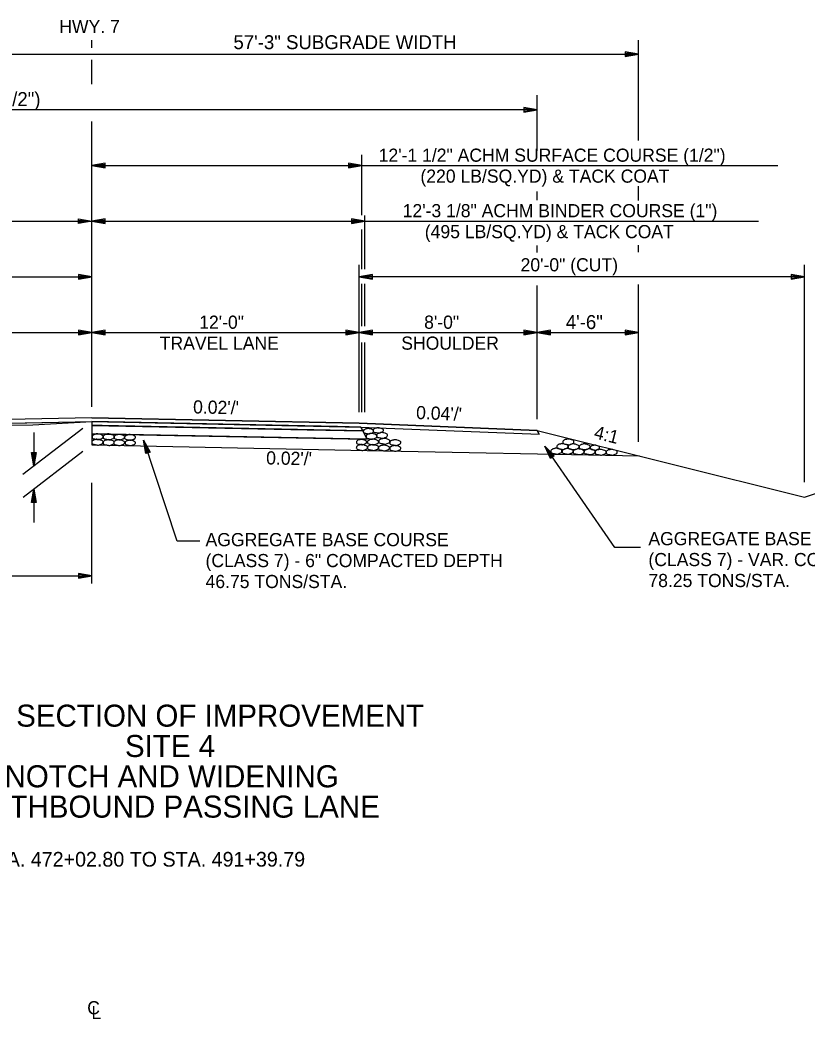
# Model space of a CAD drawing. Extents: x 1398183 to 1398373, y 1967240 to 1968889.
# Drawn here: x 1398250.61 to 1398285.95, y 1967604.2 to 1967649.04 of the extents above; entities that cross this region are included whole.
import ezdxf

# ---------------------------------------------------------------- set-up
doc = ezdxf.new("R2010")
doc.units = 0
for name, color, linetype in [('1', 7, 'Continuous'), ('10', 7, 'Continuous'), ('19', 7, 'Continuous'), ('42', 7, 'Continuous'), ('7', 7, 'Continuous'), ('Level 1', 7, 'Continuous')]:
    doc.layers.add(name, color=color, linetype=linetype)

# ---------------------------------------------------------------- blocks, each defined once
blk = doc.blocks.new('ROCKS')
at = {"layer": '1'}
blk.add_spline([(0.013, 0.06), (0.053, 0.053), (0.107, 0.033), (0.133, 0.013), (0.133, -0.007), (0.12, -0.033), (0.107, -0.04), (0.073, -0.053), (0.033, -0.067), (0.013, -0.067), (-0.02, -0.06), (-0.06, -0.053), (-0.087, -0.047), (-0.113, -0.02), (-0.113, -0.007), (-0.107, 0.02), (-0.087, 0.033), (-0.067, 0.047), (-0.033, 0.053), (-0.02, 0.06), (0.013, 0.06)], degree=3, dxfattribs=at)

msp = doc.modelspace()

# ---------------------------------------------------------------- linework, layer by layer
at = {"layer": '19'}
for p, q in [((1398278.376, 1967643.623), (1398278.376, 1967648.126)), ((1398221.092, 1967647.504), (1398278.376, 1967647.504)), ((1398277.776, 1967647.61), (1398277.776, 1967647.4)), ((1398278.376, 1967647.504), (1398277.776, 1967647.61)), ((1398278.216, 1967647.519), (1398277.776, 1967647.555)), ((1398277.776, 1967647.4), (1398278.376, 1967647.504)), ((1398277.776, 1967647.45), (1398278.216, 1967647.489)), ((1398273.831, 1967643.17), (1398273.831, 1967645.662)), ((1398273.231, 1967645.11), (1398273.231, 1967644.9)), ((1398273.831, 1967645.004), (1398273.231, 1967645.11)), ((1398273.671, 1967645.019), (1398273.231, 1967645.055)), ((1398273.831, 1967645.004), (1398223.831, 1967645.005)), ((1398273.231, 1967644.9), (1398273.831, 1967645.004)), ((1398273.231, 1967644.95), (1398273.671, 1967644.989)), ((1398265.966, 1967640.272), (1398265.966, 1967642.987)), ((1398254.438, 1967642.609), (1398253.838, 1967642.504)), ((1398253.838, 1967642.504), (1398254.438, 1967642.399)), ((1398253.838, 1967642.504), (1398284.641, 1967642.504)), ((1398254.438, 1967642.554), (1398253.998, 1967642.519)), ((1398253.998, 1967642.489), (1398254.438, 1967642.449)), ((1398254.438, 1967642.399), (1398254.438, 1967642.609)), ((1398265.366, 1967642.61), (1398265.366, 1967642.4)), ((1398265.966, 1967642.504), (1398265.366, 1967642.61)), ((1398265.806, 1967642.519), (1398265.366, 1967642.555)), ((1398265.366, 1967642.4), (1398265.966, 1967642.504)), ((1398265.366, 1967642.45), (1398265.806, 1967642.489)), ((1398278.377, 1967640.93), (1398278.377, 1967641.575)), ((1398273.829, 1967640.951), (1398273.829, 1967641.345)), ((1398253.238, 1967639.899), (1398253.238, 1967640.109)), ((1398253.238, 1967640.109), (1398253.838, 1967640.004)), ((1398254.438, 1967640.109), (1398253.838, 1967640.004)), ((1398254.438, 1967639.899), (1398254.438, 1967640.109)), ((1398265.503, 1967640.109), (1398265.503, 1967639.899)), ((1398266.103, 1967640.004), (1398265.503, 1967640.109)), ((1398266.103, 1967637.855), (1398266.103, 1967640.269)), ((1398229.838, 1967640.005), (1398283.763, 1967640.004)), ((1398253.238, 1967640.054), (1398253.678, 1967640.019)), ((1398253.838, 1967640.004), (1398253.238, 1967639.899)), ((1398253.678, 1967639.989), (1398253.238, 1967639.949)), ((1398253.838, 1967640.004), (1398254.438, 1967639.899)), ((1398254.438, 1967640.054), (1398253.998, 1967640.019)), ((1398253.998, 1967639.989), (1398254.438, 1967639.949)), ((1398265.943, 1967640.019), (1398265.503, 1967640.054)), ((1398265.503, 1967639.899), (1398266.103, 1967640.004)), ((1398265.503, 1967639.949), (1398265.943, 1967639.989)), ((1398265.966, 1967637.855), (1398265.966, 1967639.628)), ((1398273.829, 1967638.603), (1398273.829, 1967638.909)), ((1398278.378, 1967638.623), (1398278.378, 1967638.929)), ((1398265.838, 1967631.437), (1398265.838, 1967638.051)), ((1398285.838, 1967628.288), (1398285.838, 1967638.051)), ((1398241.838, 1967637.504), (1398253.838, 1967637.504)), ((1398253.238, 1967637.61), (1398253.238, 1967637.4)), ((1398253.838, 1967637.504), (1398253.238, 1967637.61)), ((1398253.678, 1967637.519), (1398253.238, 1967637.555)), ((1398253.238, 1967637.4), (1398253.838, 1967637.504)), ((1398253.238, 1967637.45), (1398253.678, 1967637.489)), ((1398266.438, 1967637.609), (1398265.838, 1967637.505)), ((1398285.838, 1967637.504), (1398265.838, 1967637.505)), ((1398265.838, 1967637.505), (1398266.438, 1967637.399)), ((1398266.438, 1967637.554), (1398265.998, 1967637.519)), ((1398265.998, 1967637.489), (1398266.438, 1967637.449)), ((1398266.438, 1967637.399), (1398266.438, 1967637.609)), ((1398285.238, 1967637.61), (1398285.238, 1967637.4)), ((1398285.838, 1967637.504), (1398285.238, 1967637.61)), ((1398285.678, 1967637.519), (1398285.238, 1967637.555)), ((1398285.238, 1967637.4), (1398285.838, 1967637.504)), ((1398285.238, 1967637.45), (1398285.678, 1967637.489)), ((1398265.966, 1967635.302), (1398265.966, 1967637.203)), ((1398266.103, 1967635.297), (1398266.103, 1967637.201)), ((1398273.838, 1967631.117), (1398273.838, 1967637.116)), ((1398278.38, 1967630.101), (1398278.378, 1967637.173)), ((1398241.838, 1967635.004), (1398253.838, 1967635.004)), ((1398253.238, 1967635.11), (1398253.238, 1967634.9)), ((1398253.838, 1967635.004), (1398253.238, 1967635.11)), ((1398253.678, 1967635.019), (1398253.238, 1967635.055)), ((1398253.238, 1967634.9), (1398253.838, 1967635.004)), ((1398253.238, 1967634.95), (1398253.678, 1967634.989)), ((1398254.438, 1967635.109), (1398253.838, 1967635.004)), ((1398253.838, 1967635.004), (1398254.438, 1967634.899)), ((1398253.838, 1967635.004), (1398265.838, 1967635.004)), ((1398254.438, 1967635.054), (1398253.998, 1967635.019)), ((1398253.998, 1967634.989), (1398254.438, 1967634.949)), ((1398254.438, 1967634.899), (1398254.438, 1967635.109)), ((1398265.238, 1967635.11), (1398265.238, 1967634.9)), ((1398265.838, 1967635.004), (1398265.238, 1967635.11)), ((1398265.678, 1967635.019), (1398265.238, 1967635.055)), ((1398265.238, 1967634.9), (1398265.838, 1967635.004)), ((1398265.238, 1967634.95), (1398265.678, 1967634.989)), ((1398266.438, 1967635.109), (1398265.838, 1967635.004)), ((1398265.838, 1967635.004), (1398266.438, 1967634.899)), ((1398265.838, 1967635.004), (1398273.838, 1967635.004)), ((1398266.438, 1967635.054), (1398265.998, 1967635.019)), ((1398265.998, 1967634.989), (1398266.438, 1967634.949)), ((1398266.438, 1967634.899), (1398266.438, 1967635.109)), ((1398273.238, 1967635.11), (1398273.238, 1967634.9)), ((1398273.838, 1967635.004), (1398273.238, 1967635.11)), ((1398273.678, 1967635.019), (1398273.238, 1967635.055)), ((1398273.238, 1967634.9), (1398273.838, 1967635.004)), ((1398273.238, 1967634.95), (1398273.678, 1967634.989)), ((1398274.438, 1967635.109), (1398273.838, 1967635.004)), ((1398273.838, 1967635.004), (1398278.38, 1967635.004)), ((1398273.838, 1967635.004), (1398274.438, 1967634.899)), ((1398274.438, 1967635.054), (1398273.998, 1967635.019)), ((1398273.998, 1967634.989), (1398274.438, 1967634.949)), ((1398274.438, 1967634.899), (1398274.438, 1967635.109)), ((1398277.78, 1967635.109), (1398277.78, 1967634.899)), ((1398278.38, 1967635.004), (1398277.78, 1967635.109)), ((1398278.22, 1967635.019), (1398277.78, 1967635.054)), ((1398277.78, 1967634.899), (1398278.38, 1967635.004)), ((1398277.78, 1967634.949), (1398278.22, 1967634.989)), ((1398265.966, 1967631.438), (1398265.966, 1967634.56)), ((1398266.103, 1967631.438), (1398266.103, 1967634.569)), ((1398253.838, 1967631.177), (1398265.838, 1967630.937)), ((1398285.838, 1967627.617), (1398296.678, 1967631.23)), ((1398253.44, 1967630.707), (1398250.738, 1967628.638)), ((1398253.838, 1967631.01), (1398253.838, 1967630.844)), ((1398253.838, 1967630.844), (1398253.838, 1967630.469)), ((1398253.838, 1967630.844), (1398266.007, 1967630.597)), ((1398265.276, 1967630.612), (1398254.302, 1967630.83)), ((1398265.838, 1967630.937), (1398273.838, 1967630.617)), ((1398265.922, 1967630.767), (1398266.007, 1967630.597)), ((1398251.24, 1967630.522), (1398251.24, 1967629.022)), ((1398253.838, 1967630.469), (1398253.838, 1967629.969)), ((1398266.197, 1967630.218), (1398253.838, 1967630.469)), ((1398266.007, 1967630.597), (1398265.276, 1967630.612)), ((1398266.007, 1967630.597), (1398266.197, 1967630.218)), ((1398266.197, 1967630.218), (1398266.007, 1967630.597)), ((1398273.838, 1967630.617), (1398285.838, 1967627.617)), ((1398273.838, 1967630.617), (1398273.923, 1967630.447)), ((1398256.267, 1967629.575), (1398256.166, 1967630.174)), ((1398256.166, 1967630.174), (1398256.464, 1967629.643)), ((1398257.677, 1967625.638), (1398256.167, 1967630.171)), ((1398256.314, 1967629.592), (1398256.204, 1967630.018)), ((1398256.23, 1967630.028), (1398256.413, 1967629.628)), ((1398265.353, 1967630.233), (1398266.197, 1967630.218)), ((1398277.318, 1967625.357), (1398274.172, 1967629.909)), ((1398274.425, 1967629.357), (1398274.172, 1967629.909)), ((1398274.172, 1967629.909), (1398274.598, 1967629.474)), ((1398253.44, 1967629.664), (1398250.758, 1967627.611)), ((1398251.135, 1967629.622), (1398251.345, 1967629.622)), ((1398251.24, 1967629.022), (1398251.135, 1967629.622)), ((1398251.225, 1967629.182), (1398251.185, 1967629.622)), ((1398251.345, 1967629.622), (1398251.24, 1967629.022)), ((1398251.29, 1967629.622), (1398251.255, 1967629.182)), ((1398256.464, 1967629.643), (1398256.267, 1967629.575)), ((1398274.466, 1967629.385), (1398274.249, 1967629.769)), ((1398274.272, 1967629.785), (1398274.553, 1967629.446)), ((1398274.598, 1967629.474), (1398274.425, 1967629.357)), ((1398253.838, 1967623.741), (1398253.838, 1967628.256)), ((1398251.135, 1967627.38), (1398251.24, 1967627.98)), ((1398251.185, 1967627.38), (1398251.225, 1967627.82)), ((1398251.24, 1967627.98), (1398251.345, 1967627.38)), ((1398251.24, 1967627.98), (1398251.24, 1967626.48)), ((1398251.255, 1967627.82), (1398251.29, 1967627.38)), ((1398251.345, 1967627.38), (1398251.135, 1967627.38)), ((1398258.69, 1967625.638), (1398257.677, 1967625.638)), ((1398278.469, 1967625.357), (1398277.318, 1967625.357)), ((1398229.838, 1967624.091), (1398253.838, 1967624.091)), ((1398253.238, 1967624.196), (1398253.238, 1967623.986)), ((1398253.838, 1967624.091), (1398253.238, 1967624.196)), ((1398253.678, 1967624.106), (1398253.238, 1967624.141)), ((1398253.238, 1967623.986), (1398253.838, 1967624.091)), ((1398253.238, 1967624.036), (1398253.678, 1967624.076))]:
    msp.add_line(p, q, dxfattribs=at)
for points in [[(1398223.753, 1967630.287), (1398229.753, 1967630.527), (1398253.838, 1967631.01), (1398265.922, 1967630.767), (1398273.923, 1967630.447), (1398273.838, 1967630.617), (1398265.837, 1967630.937), (1398253.838, 1967631.177), (1398229.838, 1967630.697), (1398223.838, 1967630.457)], [(1398253.837, 1967631.011), (1398253.837, 1967630.844), (1398254.646, 1967630.828), (1398263.512, 1967630.647), (1398266.008, 1967630.597), (1398265.923, 1967630.767), (1398264.865, 1967630.788), (1398254.582, 1967630.996)]]:
    msp.add_lwpolyline(points, close=True, dxfattribs=at)
for points in [[(1398253.838, 1967631.177), (1398241.838, 1967630.937), (1398229.838, 1967630.697)], [(1398223.753, 1967630.287), (1398229.753, 1967630.527), (1398241.838, 1967630.77), (1398253.838, 1967631.01), (1398265.922, 1967630.767), (1398273.923, 1967630.447)], [(1398254.302, 1967630.83), (1398253.838, 1967630.844), (1398253.838, 1967630.469)], [(1398253.838, 1967630.469), (1398254.429, 1967630.452), (1398265.353, 1967630.233)], [(1398253.838, 1967629.969), (1398266.197, 1967629.718), (1398278.422, 1967629.471)]]:
    msp.add_lwpolyline(points, dxfattribs=at)
at = {"layer": '42'}
msp.add_lwpolyline([(1398241.847, 1967630.754), (1398251.195, 1967630.869), (1398253.837, 1967631.011)], dxfattribs=at)
at = {"layer": '7'}
for p, q in [((1398253.838, 1967647.782), (1398253.838, 1967648.126)), ((1398253.838, 1967646.163), (1398253.838, 1967647.252)), ((1398253.838, 1967631.677), (1398253.837, 1967644.479))]:
    msp.add_line(p, q, dxfattribs=at)

# ---------------------------------------------------------------- block references
at = {"layer": 'Level 1'}
for p, xscale, yscale, rotation in [((1398266.239, 1967630.587), 1.8771740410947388, 1.8771740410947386, -0.173618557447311), ((1398266.682, 1967630.623), 1.849824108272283, 1.8498241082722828, -0.17361855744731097), ((1398254.079, 1967630.337), 2.011654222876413, 2.0116542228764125, -0.17361855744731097), ((1398254.578, 1967630.335), 2.011654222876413, 2.0116542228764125, -0.17361855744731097), ((1398255.058, 1967630.321), 1.907051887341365, 1.9070518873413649, -0.173618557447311), ((1398255.534, 1967630.309), 1.9598639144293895, 1.959863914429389, -0.173618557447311), ((1398266.378, 1967630.358), 2.011654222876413, 2.0116542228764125, -0.17361855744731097), ((1398266.846, 1967630.399), 2.011654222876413, 2.0116542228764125, -0.17361855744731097), ((1398266.955, 1967630.135), 2.011654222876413, 2.0116542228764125, -0.17361855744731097), ((1398254.071, 1967630.095), 2.011654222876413, 2.0116542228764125, -0.17361855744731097), ((1398254.575, 1967630.077), 2.011654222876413, 2.0116542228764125, -0.17361855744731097), ((1398255.048, 1967630.073), 1.9974694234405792, 1.9974694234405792, -0.17361855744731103), ((1398255.545, 1967630.064), 1.890205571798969, 1.8902055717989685, -0.17361855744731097), ((1398265.942, 1967629.856), 2.011654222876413, 2.0116542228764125, -0.17361855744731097), ((1398265.93, 1967630.099), 1.8429465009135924, 1.8429465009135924, -0.17361855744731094), ((1398266.444, 1967629.855), 2.011654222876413, 2.0116542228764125, -0.17361855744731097), ((1398266.445, 1967630.103), 2.011654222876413, 2.0116542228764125, -0.17361855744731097), ((1398266.937, 1967629.835), 2.011654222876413, 2.0116542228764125, -0.17361855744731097), ((1398267.441, 1967629.817), 2.011654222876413, 2.0116542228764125, -0.17361855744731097), ((1398267.444, 1967630.075), 2.011654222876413, 2.0116542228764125, -0.17361855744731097), ((1398274.676, 1967629.692), 2.011654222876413, 2.0116542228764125, -0.17361855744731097), ((1398274.676, 1967629.692), 2.011654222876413, 2.0116542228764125, -0.17361855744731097), ((1398274.946, 1967629.899), 2.011654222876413, 2.0116542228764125, -0.17361855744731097), ((1398275.18, 1967629.682), 2.011654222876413, 2.0116542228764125, -0.17361855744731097), ((1398275.18, 1967629.682), 2.011654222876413, 2.0116542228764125, -0.17361855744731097), ((1398275.215, 1967630.107), 2.011654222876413, 2.0116542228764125, -0.17361855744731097), ((1398275.446, 1967629.887), 2.011654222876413, 2.0116542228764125, -0.17361855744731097), ((1398275.672, 1967629.664), 2.011654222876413, 2.0116542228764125, -0.17361855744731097), ((1398275.672, 1967629.664), 2.011654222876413, 2.0116542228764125, -0.17361855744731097), ((1398275.942, 1967629.887), 2.011654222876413, 2.0116542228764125, -0.17361855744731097), ((1398276.162, 1967629.664), 2.011654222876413, 2.0116542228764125, -0.17361855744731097), ((1398276.162, 1967629.664), 2.011654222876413, 2.0116542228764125, -0.17361855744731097), ((1398276.404, 1967629.848), 1.7335100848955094, 1.7335100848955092, -0.173618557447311), ((1398276.656, 1967629.644), 2.011654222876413, 2.0116542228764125, -0.17361855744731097), ((1398276.656, 1967629.644), 2.011654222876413, 2.0116542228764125, -0.17361855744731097), ((1398277.158, 1967629.644), 2.011654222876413, 2.0116542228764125, -0.17361855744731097), ((1398277.158, 1967629.644), 2.011654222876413, 2.0116542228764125, -0.17361855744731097)]:
    msp.add_blockref('ROCKS', p, dxfattribs=dict(at, xscale=xscale, yscale=yscale, rotation=rotation))

# ---------------------------------------------------------------- texts
at = {"layer": '10'}
for s, height, p in [('20\'-0" (CUT)', 0.59001, (1398273.088, 1967637.756)), ('12\'-0"', 0.59, (1398258.66, 1967635.179)), ('8\'-0"', 0.59, (1398268.758, 1967635.179)), ('TRAVEL LANE', 0.59001, (1398256.888, 1967634.239)), ('SHOULDER', 0.59, (1398267.731, 1967634.239))]:
    msp.add_text(s, height=height, dxfattribs=at).set_placement(p)
for s, rotation, p in [("0.04'/'", 357.7094, (1398268.388, 1967631.13)), ('4:1', 345.9638, (1398276.345, 1967630.269))]:
    msp.add_text(s, height=0.59, rotation=rotation, dxfattribs=at).set_placement(p)
at = {"layer": '19'}
for s, height, p in [('HWY. 7', 0.59, (1398252.378, 1967648.449)), ('57\'-3" SUBGRADE WIDTH', 0.625, (1398260.196, 1967647.73)), ('50\'-0" ACHM SURFACE COURSE (1/2")', 0.625, (1398236.433, 1967645.176)), ('4\'-6"', 0.625, (1398275.116, 1967635.166)), ('TYPICAL SECTION OF IMPROVEMENT', 0.98999, (1398244.558, 1967617.317)), ('SITE 4', 0.99, (1398255.327, 1967615.956)), ('NOTCH AND WIDENING', 0.98999, (1398249.921, 1967614.595)), ('SOUTHBOUND PASSING LANE', 0.98999, (1398247.274, 1967613.234)), ('STA. 472+02.80 TO STA. 491+39.79', 0.65999, (1398248.893, 1967611.036)), ('C', 0.59, (1398253.633, 1967604.406)), ('L', 0.59, (1398253.821, 1967604.195))]:
    msp.add_text(s, height=height, dxfattribs=at).set_placement(p)
for s, height, rotation, p in [("0.02'/'", 0.59, 358.8542, (1398258.381, 1967631.381)), ("0.02'/'", 0.59, 358.8542, (1398261.661, 1967629.092)), ('AGGREGATE BASE COURSE', 0.59001, 360, (1398258.944, 1967625.419)), ('AGGREGATE BASE COURSE', 0.59001, 360, (1398278.826, 1967625.464)), ('(CLASS 7) - 6" COMPACTED DEPTH', 0.59001, 360, (1398258.944, 1967624.479)), ('(CLASS 7) - VAR. COMPACTED DEPTH', 0.59001, 360, (1398278.826, 1967624.524)), ('46.75 TONS/STA.', 0.59001, 360, (1398258.944, 1967623.539)), ('78.25 TONS/STA.', 0.59001, 360, (1398278.826, 1967623.584))]:
    msp.add_text(s, height=height, rotation=rotation, dxfattribs=at).set_placement(p)
at = {"layer": '42'}
for s, p in [('12\'-1 1/2" ACHM SURFACE COURSE (1/2")', (1398266.717, 1967642.676)), ('(220 LB/SQ.YD) & TACK COAT', (1398268.591, 1967641.736)), ('12\'-3 1/8" ACHM BINDER COURSE (1")', (1398267.795, 1967640.185)), ('(495 LB/SQ.YD) & TACK COAT', (1398268.787, 1967639.245))]:
    msp.add_text(s, height=0.59001, rotation=360, dxfattribs=at).set_placement(p)

doc.saveas('drawing.dxf')
